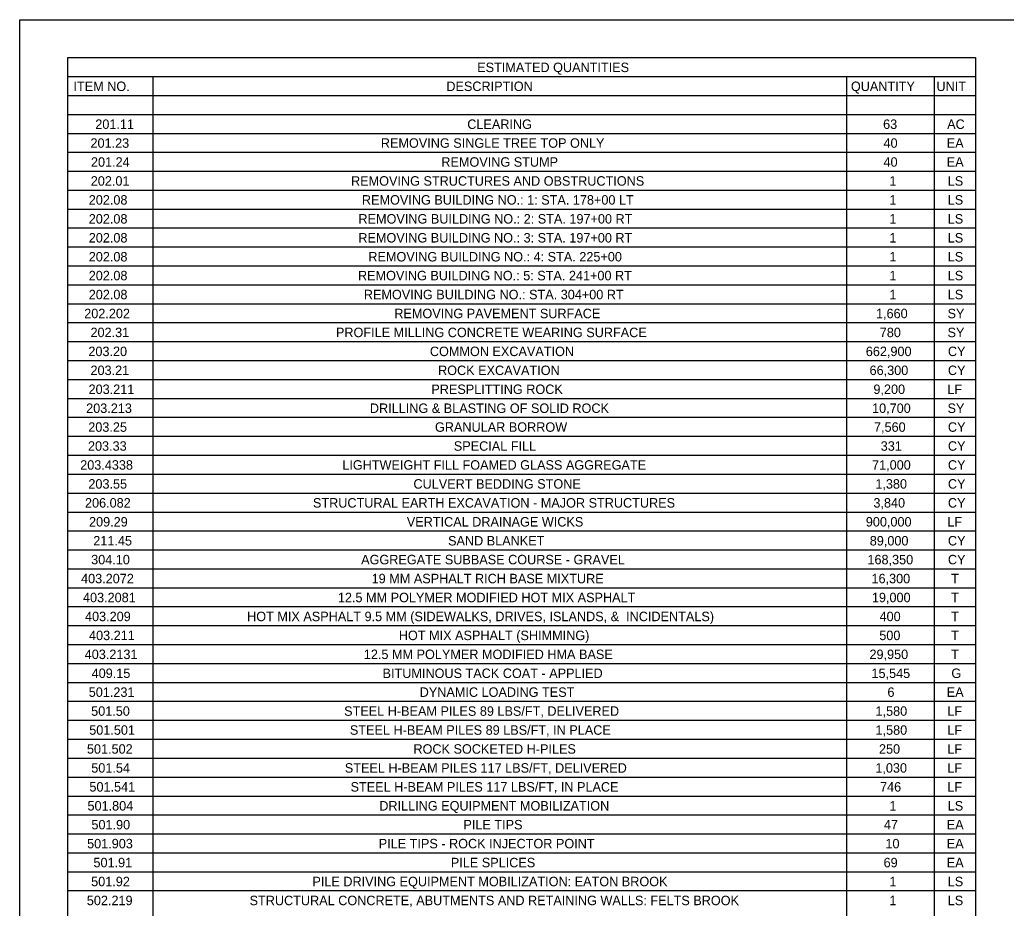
# Model space of a CAD drawing. Extents: x -18.7 to 5.6, y -2.7 to 4.
# Drawn here: x -17.663 to -16.637, y 3.09 to 4.014 of the extents above; entities that cross this region are included whole.
import ezdxf

# ---------------------------------------------------------------- set-up
doc = ezdxf.new("R2010")
doc.units = 0
doc.layers.add('ANNOTATION', color=7, linetype='Continuous')
doc.layers.add('BORDER', color=7, linetype='Continuous')

msp = doc.modelspace()

# ---------------------------------------------------------------- linework, layer by layer
at = {"layer": 'ANNOTATION'}
msp.add_lwpolyline([(-17.663, 4.0141), (-13.3075, 4.0141), (-13.3075, 2.1719), (-17.663, 2.1719)], close=True, dxfattribs=at)
at = {"layer": 'BORDER'}
for p, q in [((-17.613, 3.9551), (-16.6688, 3.9551)), ((-17.5245, 3.9551), (-17.5245, 2.2424)), ((-16.8032, 3.9551), (-16.8032, 2.2424)), ((-16.7118, 3.9551), (-16.7118, 2.2424)), ((-17.613, 3.9354), (-16.6688, 3.9354)), ((-17.613, 3.9157), (-16.6688, 3.9157)), ((-17.613, 3.896), (-16.6688, 3.896)), ((-17.613, 3.8764), (-16.6688, 3.8764)), ((-17.613, 3.8567), (-16.6688, 3.8567)), ((-17.613, 3.837), (-16.6688, 3.837)), ((-17.613, 3.8173), (-16.6688, 3.8173)), ((-17.613, 3.7976), (-16.6688, 3.7976)), ((-17.613, 3.7779), (-16.6688, 3.7779)), ((-17.613, 3.7582), (-16.6688, 3.7582)), ((-17.613, 3.7386), (-16.6688, 3.7386)), ((-17.613, 3.7189), (-16.6688, 3.7189)), ((-17.613, 3.6992), (-16.6688, 3.6992)), ((-17.613, 3.6795), (-16.6688, 3.6795)), ((-17.613, 3.6598), (-16.6688, 3.6598)), ((-17.613, 3.6401), (-16.6688, 3.6401)), ((-17.613, 3.6204), (-16.6688, 3.6204)), ((-17.613, 3.6008), (-16.6688, 3.6008)), ((-17.613, 3.5811), (-16.6688, 3.5811)), ((-17.613, 3.5614), (-16.6688, 3.5614)), ((-17.613, 3.5417), (-16.6688, 3.5417)), ((-17.613, 3.522), (-16.6688, 3.522)), ((-17.613, 3.5023), (-16.6688, 3.5023)), ((-17.613, 3.4826), (-16.6688, 3.4826)), ((-17.613, 3.463), (-16.6688, 3.463)), ((-17.613, 3.4433), (-16.6688, 3.4433)), ((-17.613, 3.4236), (-16.6688, 3.4236)), ((-17.613, 3.4039), (-16.6688, 3.4039)), ((-17.613, 3.3842), (-16.6688, 3.3842)), ((-17.613, 3.3645), (-16.6688, 3.3645)), ((-17.613, 3.3448), (-16.6688, 3.3448)), ((-17.613, 3.3251), (-16.6688, 3.3251)), ((-17.613, 3.3055), (-16.6688, 3.3055)), ((-17.613, 3.2858), (-16.6688, 3.2858)), ((-17.613, 3.2661), (-16.6688, 3.2661)), ((-17.613, 3.2464), (-16.6688, 3.2464)), ((-17.613, 3.2267), (-16.6688, 3.2267)), ((-17.613, 3.207), (-16.6688, 3.207)), ((-17.613, 3.1873), (-16.6688, 3.1873)), ((-17.613, 3.1677), (-16.6688, 3.1677)), ((-17.613, 3.148), (-16.6688, 3.148)), ((-17.613, 3.1283), (-16.6688, 3.1283)), ((-17.613, 3.1086), (-16.6688, 3.1086))]:
    msp.add_line(p, q, dxfattribs=at)
msp.add_lwpolyline([(-17.613, 3.9748), (-16.6688, 3.9748), (-16.6688, 2.2424), (-17.613, 2.2424)], close=True, dxfattribs=at)

# ---------------------------------------------------------------- texts
at = {"layer": 'ANNOTATION'}
for s, height, p in [('201.11', 0.00984, (-17.5844, 3.9006)), ('CLEARING', 0.00984, (-17.1975, 3.9006)), ('63', 0.00984, (-16.765, 3.9006)), ('AC', 0.00984, (-16.6984, 3.9006)), ('201.23', 0.00984, (-17.5894, 3.881)), ('REMOVING SINGLE TREE TOP ONLY', 0.009843, (-17.2874, 3.881)), ('40', 0.00984, (-16.7646, 3.881)), ('EA', 0.00984, (-16.6988, 3.881)), ('201.24', 0.00984, (-17.5889, 3.8613)), ('REMOVING STUMP', 0.009843, (-17.2245, 3.8613)), ('40', 0.00984, (-16.7646, 3.8613)), ('EA', 0.00984, (-16.6988, 3.8613)), ('202.01', 0.00984, (-17.5891, 3.8416)), ('REMOVING STRUCTURES AND OBSTRUCTIONS', 0.009843, (-17.3184, 3.8416)), ('1', 0.00984, (-16.7585, 3.8416)), ('LS', 0.00984, (-16.6978, 3.8416)), ('202.08', 0.00984, (-17.5912, 3.8219)), ('REMOVING BUILDING NO.: 1: STA. 178+00 LT', 0.009843, (-17.3071, 3.8219)), ('1', 0.00984, (-16.7585, 3.8219)), ('LS', 0.00984, (-16.6978, 3.8219)), ('202.08', 0.00984, (-17.5912, 3.8022)), ('REMOVING BUILDING NO.: 2: STA. 197+00 RT', 0.009843, (-17.3107, 3.8022)), ('1', 0.00984, (-16.7585, 3.8022)), ('LS', 0.00984, (-16.6978, 3.8022)), ('202.08', 0.00984, (-17.5912, 3.7825)), ('REMOVING BUILDING NO.: 3: STA. 197+00 RT', 0.009843, (-17.3108, 3.7825)), ('1', 0.00984, (-16.7585, 3.7825)), ('LS', 0.00984, (-16.6978, 3.7825)), ('202.08', 0.00984, (-17.5912, 3.7628)), ('REMOVING BUILDING NO.: 4: STA. 225+00', 0.009843, (-17.3004, 3.7628)), ('1', 0.00984, (-16.7585, 3.7628)), ('LS', 0.00984, (-16.6978, 3.7628)), ('202.08', 0.00984, (-17.5912, 3.7432)), ('REMOVING BUILDING NO.: 5: STA. 241+00 RT', 0.009843, (-17.3112, 3.7432)), ('1', 0.00984, (-16.7585, 3.7432)), ('LS', 0.00984, (-16.6978, 3.7432)), ('202.08', 0.00984, (-17.5912, 3.7235)), ('REMOVING BUILDING NO.: STA. 304+00 RT', 0.009843, (-17.3051, 3.7235)), ('1', 0.00984, (-16.7585, 3.7235)), ('LS', 0.00984, (-16.6978, 3.7235)), ('202.202', 0.00984, (-17.5959, 3.7038)), ('REMOVING PAVEMENT SURFACE', 0.009843, (-17.2734, 3.7038)), ('1,660', 0.00984, (-16.7724, 3.7038)), ('SY', 0.00984, (-16.698, 3.7038)), ('202.31', 0.00984, (-17.5894, 3.6841)), ('PROFILE MILLING CONCRETE WEARING SURFACE', 0.009843, (-17.3341, 3.6841)), ('780', 0.00984, (-16.7685, 3.6841)), ('SY', 0.00984, (-16.698, 3.6841)), ('203.20', 0.00984, (-17.5916, 3.6644)), ('COMMON EXCAVATION', 0.009843, (-17.2364, 3.6644)), ('662,900', 0.00984, (-16.783, 3.6644)), ('CY', 0.00984, (-16.6976, 3.6644)), ('203.21', 0.00984, (-17.5894, 3.6447)), ('ROCK EXCAVATION', 0.009843, (-17.2279, 3.6447)), ('66,300', 0.00984, (-16.7791, 3.6447)), ('CY', 0.00984, (-16.6976, 3.6447)), ('203.211', 0.00984, (-17.5914, 3.625)), ('PRESPLITTING ROCK', 0.009843, (-17.2349, 3.625)), ('9,200', 0.00984, (-16.7751, 3.625)), ('LF', 0.00984, (-16.6982, 3.625)), ('203.213', 0.00984, (-17.5939, 3.6053)), ('DRILLING & BLASTING OF SOLID ROCK       ', 0.009843, (-17.2988, 3.6053)), ('10,700', 0.00984, (-16.7765, 3.6053)), ('SY', 0.00984, (-16.698, 3.6053)), ('203.25', 0.00984, (-17.5917, 3.5857)), ('GRANULAR BORROW', 0.009843, (-17.2311, 3.5857)), ('7,560', 0.00984, (-16.7745, 3.5857)), ('CY', 0.00984, (-16.6976, 3.5857)), ('203.33', 0.00984, (-17.592, 3.566)), ('SPECIAL FILL', 0.009843, (-17.2115, 3.566)), ('331', 0.00984, (-16.7675, 3.566)), ('CY', 0.00984, (-16.6976, 3.566)), ('203.4338', 0.00984, (-17.6001, 3.5463)), ('LIGHTWEIGHT FILL FOAMED GLASS AGGREGATE', 0.009843, (-17.3275, 3.5463)), ('71,000', 0.00984, (-16.7765, 3.5463)), ('CY', 0.00984, (-16.6976, 3.5463)), ('203.55', 0.00984, (-17.5916, 3.5266)), ('CULVERT BEDDING STONE', 0.009843, (-17.2535, 3.5266)), ('1,380', 0.00984, (-16.7731, 3.5266)), ('CY', 0.00984, (-16.6976, 3.5266)), ('206.082', 0.00984, (-17.5951, 3.5069)), ('STRUCTURAL EARTH EXCAVATION - MAJOR STRUCTURES', 0.009843, (-17.358, 3.5069)), ('3,840', 0.00984, (-16.7751, 3.5069)), ('CY', 0.00984, (-16.6976, 3.5069)), ('209.29', 0.00984, (-17.5909, 3.4872)), ('VERTICAL DRAINAGE WICKS', 0.009843, (-17.2604, 3.4872)), ('900,000', 0.00984, (-16.783, 3.4872)), ('LF', 0.00984, (-16.6982, 3.4872)), ('211.45', 0.00984, (-17.5865, 3.4675)), ('SAND BLANKET', 0.009843, (-17.2175, 3.4675)), ('89,000', 0.00984, (-16.7789, 3.4675)), ('CY', 0.00984, (-16.6976, 3.4675)), ('304.10', 0.00984, (-17.5887, 3.4479)), ('AGGREGATE SUBBASE COURSE - GRAVEL', 0.009843, (-17.3079, 3.4479)), ('168,350', 0.00984, (-16.7813, 3.4479)), ('CY', 0.00984, (-16.6976, 3.4479)), ('403.2072', 0.00984, (-17.5992, 3.4282)), ('19 MM ASPHALT RICH BASE MIXTURE', 0.009843, (-17.297, 3.4282)), ('16,300', 0.00984, (-16.7771, 3.4282)), ('T', 0.00984, (-16.6943, 3.4282)), ('403.2081', 0.00984, (-17.5972, 3.4085)), ('12.5 MM POLYMER MODIFIED HOT MIX ASPHALT', 0.009843, (-17.3321, 3.4085)), ('19,000', 0.00984, (-16.7767, 3.4085)), ('T', 0.00984, (-16.6943, 3.4085)), ('403.209', 0.00984, (-17.5951, 3.3888)), ('HOT MIX ASPHALT 9.5 MM (SIDEWALKS, DRIVES, ISLANDS, &  INCIDENTALS)', 0.009843, (-17.4265, 3.3888)), ('400', 0.00984, (-16.7687, 3.3888)), ('T', 0.00984, (-16.6943, 3.3888)), ('403.211', 0.00984, (-17.5909, 3.3691)), ('HOT MIX ASPHALT (SHIMMING)', 0.009843, (-17.2687, 3.3691)), ('500', 0.00984, (-16.769, 3.3691)), ('T', 0.00984, (-16.6943, 3.3691)), ('403.2131', 0.00984, (-17.5954, 3.3494)), ('12.5 MM POLYMER MODIFIED HMA BASE', 0.009843, (-17.3051, 3.3494)), ('29,950', 0.00984, (-16.7792, 3.3494)), ('T', 0.00984, (-16.6943, 3.3494)), ('409.15', 0.00984, (-17.5882, 3.3297)), ('BITUMINOUS TACK COAT - APPLIED', 0.009843, (-17.2856, 3.3297)), ('15,545', 0.00984, (-16.7771, 3.3297)), ('G', 0.00984, (-16.694, 3.3297)), ('501.231', 0.00984, (-17.5912, 3.3101)), ('DYNAMIC LOADING TEST', 0.009843, (-17.247, 3.3101)), ('6', 0.00984, (-16.7605, 3.3101)), ('EA', 0.00984, (-16.6988, 3.3101)), ('501.50', 0.00984, (-17.5887, 3.2904)), ('STEEL H-BEAM PILES 89 LBS/FT, DELIVERED', 0.009843, (-17.3256, 3.2904)), ('1,580', 0.00984, (-16.7729, 3.2904)), ('LF', 0.00984, (-16.6982, 3.2904)), ('501.501', 0.00984, (-17.5907, 3.2707)), ('STEEL H-BEAM PILES 89 LBS/FT, IN PLACE', 0.009843, (-17.3196, 3.2707)), ('1,580', 0.00984, (-16.7729, 3.2707)), ('LF', 0.00984, (-16.6982, 3.2707)), ('501.502', 0.00984, (-17.5931, 3.251)), ('ROCK SOCKETED H-PILES', 0.009843, (-17.2535, 3.251)), ('250', 0.00984, (-16.7693, 3.251)), ('LF', 0.00984, (-16.6982, 3.251)), ('501.54', 0.00984, (-17.5886, 3.2313)), ('STEEL H-BEAM PILES 117 LBS/FT, DELIVERED', 0.009843, (-17.3249, 3.2313)), ('1,030', 0.00984, (-16.7731, 3.2313)), ('LF', 0.00984, (-16.6982, 3.2313)), ('STEEL H-BEAM PILES 117 LBS/FT, IN PLACE', 0.009843, (-17.3189, 3.2116)), ('501.541', 0.00984, (-17.5905, 3.2116)), ('746', 0.00984, (-16.7682, 3.2116)), ('LF', 0.00984, (-16.6982, 3.2116)), ('501.804', 0.00984, (-17.5925, 3.1919)), ('DRILLING EQUIPMENT MOBILIZATION', 0.009843, (-17.289, 3.1919)), ('1', 0.00984, (-16.7585, 3.1919)), ('LS', 0.00984, (-16.6978, 3.1919)), ('501.90', 0.00984, (-17.5884, 3.1723)), ('PILE TIPS', 0.00984, (-17.2015, 3.1723)), ('47', 0.00984, (-16.7642, 3.1723)), ('EA', 0.00984, (-16.6988, 3.1723)), ('501.903', 0.00984, (-17.5929, 3.1526)), ('PILE TIPS - ROCK INJECTOR POINT', 0.009843, (-17.2896, 3.1526)), ('10', 0.00984, (-16.7626, 3.1526)), ('EA', 0.00984, (-16.6988, 3.1526)), ('501.91', 0.00984, (-17.5863, 3.1329)), ('PILE SPLICES', 0.009843, (-17.2146, 3.1329)), ('69', 0.00984, (-16.7645, 3.1329)), ('EA', 0.00984, (-16.6988, 3.1329)), ('501.92', 0.00984, (-17.5887, 3.1132)), ('PILE DRIVING EQUIPMENT MOBILIZATION: EATON BROOK', 0.009843, (-17.3586, 3.1132)), ('1', 0.00984, (-16.7585, 3.1132)), ('LS', 0.00984, (-16.6978, 3.1132)), ('502.219', 0.00984, (-17.5932, 3.0935)), ('STRUCTURAL CONCRETE, ABUTMENTS AND RETAINING WALLS: FELTS BROOK', 0.009843, (-17.4239, 3.0935)), ('1', 0.00984, (-16.7585, 3.0935)), ('LS', 0.00984, (-16.6978, 3.0935))]:
    msp.add_text(s, height=height, dxfattribs=at).set_placement(p)
at = {"layer": 'BORDER'}
for s, height, p in [('ESTIMATED QUANTITIES', 0.009843, (-17.1872, 3.9597)), ('ITEM NO.', 0.00984, (-17.6071, 3.94)), ('DESCRIPTION', 0.009843, (-17.2193, 3.94)), ('QUANTITY', 0.00984, (-16.7985, 3.94)), ('UNIT', 0.00984, (-16.7095, 3.94))]:
    msp.add_text(s, height=height, dxfattribs=at).set_placement(p)

doc.saveas('drawing.dxf')
